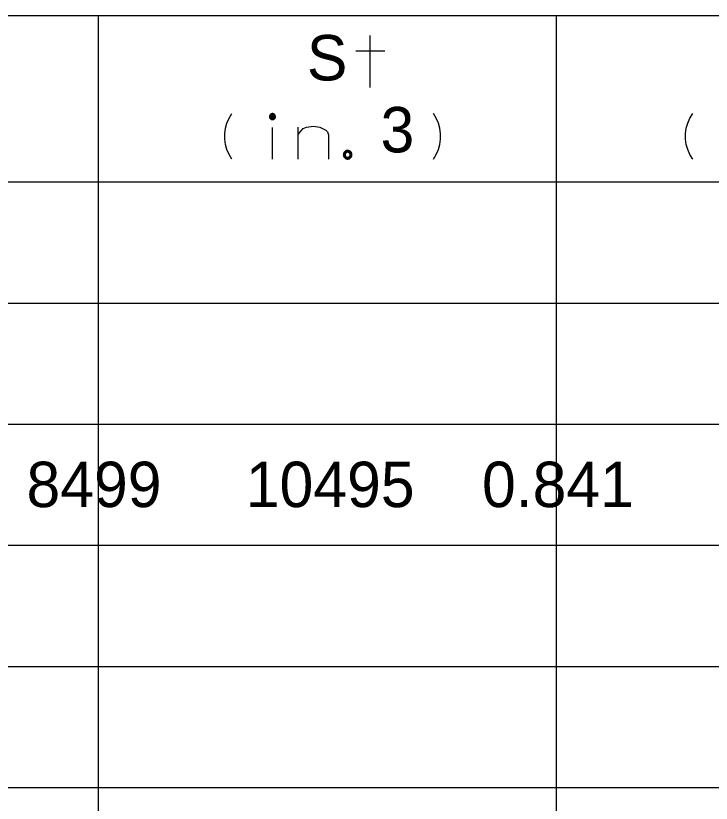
# Model space of a CAD drawing. Extents: x 635698 to 639877, y 296617 to 300175.
# Drawn here: x 639313.2 to 639359.1, y 298756.3 to 298808.3 of the extents above; entities that cross this region are included whole.
import ezdxf

# ---------------------------------------------------------------- set-up
doc = ezdxf.new("R2010")
doc.units = 0
for name, color, linetype in [('1', 7, 'Continuous'), ('2', 7, 'Continuous'), ('3', 7, 'Continuous')]:
    doc.layers.add(name, color=color, linetype=linetype)

msp = doc.modelspace()

# ---------------------------------------------------------------- linework, layer by layer
at = {"layer": '2'}
for p, q in [((639405.108, 298808.295), (639199.161, 298808.295)), ((639318.602, 298808.295), (639318.602, 298581.295)), ((639348.883, 298808.295), (639348.883, 298581.295)), ((639405.108, 298797.295), (638853.272, 298797.295)), ((639405.108, 298789.295), (638853.272, 298789.295)), ((639405.108, 298781.295), (638853.272, 298781.295)), ((639405.108, 298773.295), (638853.272, 298773.295)), ((639405.108, 298765.295), (638853.272, 298765.295)), ((639405.108, 298757.295), (638853.272, 298757.295))]:
    msp.add_line(p, q, dxfattribs=at)
for points in [[(639336.588, 298803.544), (639336.588, 298806.998)], [(639337.547, 298805.954), (639335.644, 298805.954)]]:
    msp.add_lwpolyline(points, dxfattribs=at)
at = {"layer": '3'}
for points in [[(639327.448, 298798.828), (639327.259, 298799.135), (639327.117, 298799.466), (639327.022, 298799.796), (639326.975, 298800.15), (639326.975, 298800.505), (639327.022, 298800.859), (639327.117, 298801.19), (639327.259, 298801.52), (639327.448, 298801.828)], [(639330.327, 298801.63), (639330.325, 298801.65), (639330.323, 298801.671), (639330.317, 298801.691), (639330.31, 298801.71), (639330.3, 298801.728), (639330.289, 298801.746), (639330.276, 298801.762), (639330.261, 298801.777), (639330.245, 298801.79), (639330.228, 298801.801), (639330.209, 298801.81), (639330.19, 298801.818), (639330.17, 298801.823), (639330.149, 298801.827), (639330.129, 298801.827), (639330.108, 298801.827), (639330.087, 298801.823), (639330.067, 298801.818), (639330.048, 298801.81), (639330.029, 298801.801), (639330.012, 298801.79), (639329.996, 298801.777), (639329.981, 298801.762), (639329.968, 298801.746), (639329.957, 298801.728), (639329.948, 298801.71), (639329.94, 298801.691), (639329.935, 298801.671), (639329.931, 298801.65), (639329.93, 298801.63), (639329.931, 298801.609), (639329.935, 298801.588), (639329.94, 298801.568), (639329.948, 298801.549), (639329.957, 298801.531), (639329.968, 298801.513), (639329.981, 298801.497), (639329.996, 298801.482), (639330.012, 298801.469), (639330.029, 298801.458), (639330.048, 298801.449), (639330.067, 298801.441), (639330.087, 298801.436), (639330.108, 298801.432), (639330.129, 298801.431), (639330.149, 298801.432), (639330.17, 298801.436), (639330.19, 298801.441), (639330.209, 298801.449), (639330.228, 298801.458), (639330.245, 298801.469), (639330.261, 298801.482), (639330.276, 298801.497), (639330.289, 298801.513), (639330.3, 298801.531), (639330.31, 298801.549), (639330.317, 298801.568), (639330.323, 298801.588), (639330.325, 298801.609), (639330.327, 298801.63)], [(639330.267, 298801.63), (639330.266, 298801.644), (639330.263, 298801.658), (639330.26, 298801.672), (639330.255, 298801.686), (639330.248, 298801.698), (639330.24, 298801.71), (639330.231, 298801.722), (639330.221, 298801.732), (639330.21, 298801.741), (639330.198, 298801.749), (639330.185, 298801.755), (639330.171, 298801.761), (639330.157, 298801.764), (639330.143, 298801.767), (639330.129, 298801.768), (639330.114, 298801.767), (639330.1, 298801.764), (639330.086, 298801.761), (639330.072, 298801.755), (639330.059, 298801.749), (639330.047, 298801.741), (639330.036, 298801.732), (639330.026, 298801.722), (639330.017, 298801.71), (639330.009, 298801.698), (639330.002, 298801.686), (639329.997, 298801.672), (639329.993, 298801.658), (639329.991, 298801.644), (639329.99, 298801.63), (639329.991, 298801.615), (639329.993, 298801.601), (639329.997, 298801.587), (639330.002, 298801.573), (639330.009, 298801.56), (639330.017, 298801.548), (639330.026, 298801.537), (639330.036, 298801.527), (639330.047, 298801.518), (639330.059, 298801.51), (639330.072, 298801.504), (639330.086, 298801.498), (639330.1, 298801.494), (639330.114, 298801.492), (639330.129, 298801.491), (639330.143, 298801.492), (639330.157, 298801.494), (639330.171, 298801.498), (639330.185, 298801.504), (639330.198, 298801.51), (639330.21, 298801.518), (639330.221, 298801.527), (639330.231, 298801.537), (639330.24, 298801.548), (639330.248, 298801.56), (639330.255, 298801.573), (639330.26, 298801.587), (639330.263, 298801.601), (639330.266, 298801.615), (639330.267, 298801.63)], [(639330.207, 298801.63), (639330.206, 298801.638), (639330.205, 298801.646), (639330.203, 298801.654), (639330.2, 298801.661), (639330.196, 298801.668), (639330.192, 298801.675), (639330.187, 298801.682), (639330.181, 298801.687), (639330.174, 298801.693), (639330.167, 298801.697), (639330.16, 298801.701), (639330.153, 298801.703), (639330.145, 298801.706), (639330.137, 298801.707), (639330.129, 298801.708), (639330.12, 298801.707), (639330.112, 298801.706), (639330.104, 298801.703), (639330.097, 298801.701), (639330.089, 298801.697), (639330.083, 298801.693), (639330.076, 298801.687), (639330.07, 298801.682), (639330.065, 298801.675), (639330.061, 298801.668), (639330.057, 298801.661), (639330.054, 298801.654), (639330.052, 298801.646), (639330.051, 298801.638), (639330.051, 298801.63), (639330.051, 298801.621), (639330.052, 298801.613), (639330.054, 298801.605), (639330.057, 298801.598), (639330.061, 298801.59), (639330.065, 298801.584), (639330.07, 298801.577), (639330.076, 298801.572), (639330.083, 298801.567), (639330.089, 298801.562), (639330.097, 298801.558), (639330.104, 298801.555), (639330.112, 298801.553), (639330.12, 298801.552), (639330.129, 298801.552), (639330.137, 298801.552), (639330.145, 298801.553), (639330.153, 298801.555), (639330.16, 298801.558), (639330.167, 298801.562), (639330.174, 298801.567), (639330.181, 298801.572), (639330.187, 298801.577), (639330.192, 298801.584), (639330.196, 298801.59), (639330.2, 298801.598), (639330.203, 298801.605), (639330.205, 298801.613), (639330.206, 298801.621), (639330.207, 298801.63)], [(639330.147, 298801.63), (639330.147, 298801.631), (639330.146, 298801.633), (639330.145, 298801.635), (639330.145, 298801.637), (639330.144, 298801.638), (639330.143, 298801.64), (639330.142, 298801.642), (639330.141, 298801.643), (639330.139, 298801.644), (639330.137, 298801.645), (639330.136, 298801.646), (639330.134, 298801.647), (639330.132, 298801.647), (639330.13, 298801.647), (639330.129, 298801.647), (639330.127, 298801.647), (639330.125, 298801.647), (639330.123, 298801.647), (639330.121, 298801.646), (639330.119, 298801.645), (639330.118, 298801.644), (639330.117, 298801.643), (639330.115, 298801.642), (639330.114, 298801.64), (639330.113, 298801.638), (639330.112, 298801.637), (639330.111, 298801.635), (639330.111, 298801.633), (639330.111, 298801.631), (639330.111, 298801.63), (639330.111, 298801.628), (639330.111, 298801.626), (639330.111, 298801.624), (639330.112, 298801.622), (639330.113, 298801.62), (639330.114, 298801.619), (639330.115, 298801.617), (639330.117, 298801.616), (639330.118, 298801.615), (639330.119, 298801.614), (639330.121, 298801.613), (639330.123, 298801.612), (639330.125, 298801.612), (639330.127, 298801.612), (639330.129, 298801.612), (639330.13, 298801.612), (639330.132, 298801.612), (639330.134, 298801.612), (639330.136, 298801.613), (639330.137, 298801.614), (639330.139, 298801.615), (639330.141, 298801.616), (639330.142, 298801.617), (639330.143, 298801.619), (639330.144, 298801.62), (639330.145, 298801.622), (639330.145, 298801.624), (639330.146, 298801.626), (639330.147, 298801.628), (639330.147, 298801.63)], [(639340.77, 298798.828), (639340.959, 298799.135), (639341.101, 298799.466), (639341.196, 298799.796), (639341.243, 298800.15), (639341.243, 298800.505), (639341.196, 298800.859), (639341.101, 298801.19), (639340.959, 298801.52), (639340.77, 298801.828)], [(639357.909, 298798.828), (639357.72, 298799.135), (639357.578, 298799.466), (639357.483, 298799.796), (639357.436, 298800.15), (639357.436, 298800.505), (639357.483, 298800.859), (639357.578, 298801.19), (639357.72, 298801.52), (639357.909, 298801.828)], [(639330.129, 298798.828), (639330.129, 298800.906)], [(639331.831, 298800.458), (639331.997, 298800.67), (639332.162, 298800.836), (639332.375, 298800.93), (639332.848, 298801.001), (639333.25, 298800.93), (639333.652, 298800.741), (639333.771, 298800.623), (639333.841, 298800.434), (639333.841, 298798.828)], [(639331.831, 298798.828), (639331.831, 298800.93)], [(639335.381, 298799.113), (639335.38, 298799.142), (639335.375, 298799.172), (639335.367, 298799.2), (639335.357, 298799.228), (639335.343, 298799.255), (639335.327, 298799.28), (639335.308, 298799.303), (639335.287, 298799.324), (639335.264, 298799.343), (639335.239, 298799.359), (639335.212, 298799.373), (639335.184, 298799.384), (639335.155, 298799.391), (639335.126, 298799.396), (639335.096, 298799.397), (639335.066, 298799.396), (639335.037, 298799.391), (639335.008, 298799.384), (639334.98, 298799.373), (639334.953, 298799.359), (639334.928, 298799.343), (639334.905, 298799.324), (639334.884, 298799.303), (639334.865, 298799.28), (639334.849, 298799.255), (639334.835, 298799.228), (639334.825, 298799.2), (639334.817, 298799.172), (639334.812, 298799.142), (639334.811, 298799.113), (639334.812, 298799.083), (639334.817, 298799.053), (639334.825, 298799.024), (639334.835, 298798.996), (639334.849, 298798.97), (639334.865, 298798.945), (639334.884, 298798.922), (639334.905, 298798.901), (639334.928, 298798.882), (639334.953, 298798.866), (639334.98, 298798.852), (639335.008, 298798.842), (639335.037, 298798.834), (639335.066, 298798.829), (639335.096, 298798.828), (639335.126, 298798.829), (639335.155, 298798.834), (639335.184, 298798.842), (639335.212, 298798.852), (639335.239, 298798.866), (639335.264, 298798.882), (639335.287, 298798.901), (639335.308, 298798.922), (639335.327, 298798.945), (639335.343, 298798.97), (639335.357, 298798.996), (639335.367, 298799.024), (639335.375, 298799.053), (639335.38, 298799.083), (639335.381, 298799.113)], [(639335.321, 298799.113), (639335.32, 298799.136), (639335.316, 298799.159), (639335.31, 298799.182), (639335.302, 298799.204), (639335.291, 298799.225), (639335.278, 298799.245), (639335.263, 298799.263), (639335.247, 298799.28), (639335.228, 298799.295), (639335.209, 298799.307), (639335.188, 298799.318), (639335.166, 298799.326), (639335.143, 298799.333), (639335.12, 298799.336), (639335.096, 298799.337), (639335.073, 298799.336), (639335.049, 298799.333), (639335.026, 298799.326), (639335.004, 298799.318), (639334.984, 298799.307), (639334.964, 298799.295), (639334.945, 298799.28), (639334.929, 298799.263), (639334.914, 298799.245), (639334.901, 298799.225), (639334.89, 298799.204), (639334.882, 298799.182), (639334.876, 298799.159), (639334.872, 298799.136), (639334.871, 298799.113), (639334.872, 298799.089), (639334.876, 298799.066), (639334.882, 298799.043), (639334.89, 298799.021), (639334.901, 298799), (639334.914, 298798.98), (639334.929, 298798.962), (639334.945, 298798.945), (639334.964, 298798.931), (639334.984, 298798.918), (639335.004, 298798.907), (639335.026, 298798.898), (639335.049, 298798.892), (639335.073, 298798.889), (639335.096, 298798.887), (639335.12, 298798.889), (639335.143, 298798.892), (639335.166, 298798.898), (639335.188, 298798.907), (639335.209, 298798.918), (639335.228, 298798.931), (639335.247, 298798.945), (639335.263, 298798.962), (639335.278, 298798.98), (639335.291, 298799), (639335.302, 298799.021), (639335.31, 298799.043), (639335.316, 298799.066), (639335.32, 298799.089), (639335.321, 298799.113)], [(639335.261, 298799.113), (639335.26, 298799.13), (639335.257, 298799.147), (639335.253, 298799.163), (639335.247, 298799.18), (639335.239, 298799.195), (639335.23, 298799.21), (639335.219, 298799.223), (639335.206, 298799.235), (639335.193, 298799.246), (639335.179, 298799.255), (639335.163, 298799.263), (639335.147, 298799.269), (639335.13, 298799.274), (639335.113, 298799.277), (639335.096, 298799.277), (639335.079, 298799.277), (639335.062, 298799.274), (639335.045, 298799.269), (639335.029, 298799.263), (639335.013, 298799.255), (639334.999, 298799.246), (639334.985, 298799.235), (639334.973, 298799.223), (639334.962, 298799.21), (639334.953, 298799.195), (639334.945, 298799.18), (639334.939, 298799.163), (639334.934, 298799.147), (639334.932, 298799.13), (639334.931, 298799.113), (639334.932, 298799.095), (639334.934, 298799.078), (639334.939, 298799.062), (639334.945, 298799.045), (639334.953, 298799.03), (639334.962, 298799.016), (639334.973, 298799.002), (639334.985, 298798.99), (639334.999, 298798.979), (639335.013, 298798.97), (639335.029, 298798.962), (639335.045, 298798.955), (639335.062, 298798.951), (639335.079, 298798.948), (639335.096, 298798.947), (639335.113, 298798.948), (639335.13, 298798.951), (639335.147, 298798.955), (639335.163, 298798.962), (639335.179, 298798.97), (639335.193, 298798.979), (639335.206, 298798.99), (639335.219, 298799.002), (639335.23, 298799.016), (639335.239, 298799.03), (639335.247, 298799.045), (639335.253, 298799.062), (639335.257, 298799.078), (639335.26, 298799.095), (639335.261, 298799.113)]]:
    msp.add_lwpolyline(points, dxfattribs=at)

# ---------------------------------------------------------------- texts
at = {"layer": '1'}
msp.add_text('220711      8499     10495    0.841', height=3, dxfattribs=at).set_placement((639293.794, 298775.837))
at = {"layer": '2'}
msp.add_text('S', height=3, dxfattribs=at).set_placement((639332.404, 298804.022))
at = {"layer": '3'}
msp.add_text('3', height=3, dxfattribs=at).set_placement((639337.273, 298799.269))

doc.saveas('drawing.dxf')
